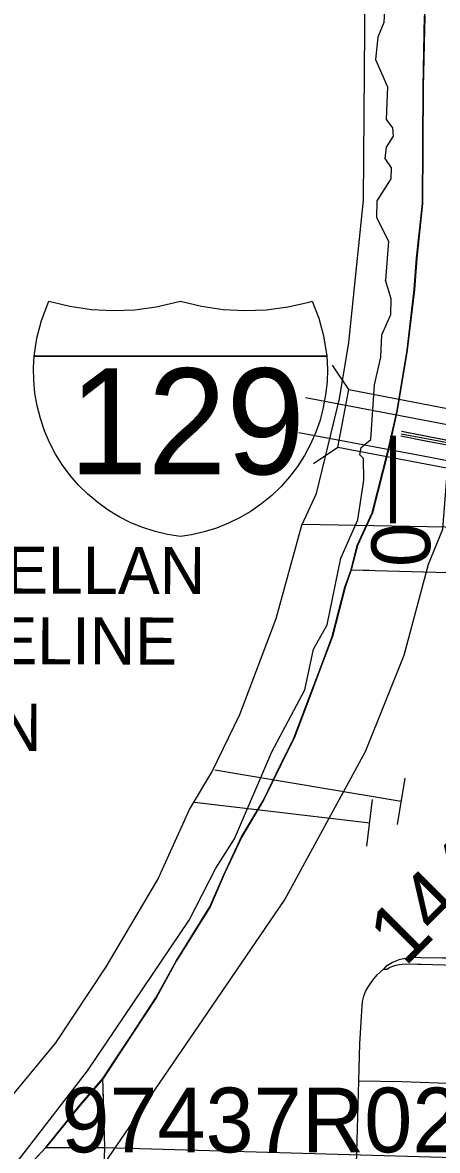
# Model space of a CAD drawing. Extents: x -157.2 to -99.3, y 12.2 to 46.2.
# Drawn here: x -147.831 to -147.125, y 32.094 to 34.011 of the extents above; entities that cross this region are included whole.
import ezdxf

# ---------------------------------------------------------------- set-up
doc = ezdxf.new("R2010")
doc.units = 0
for name, color, linetype in [('tdCoCityStreetMinor', 7, 'Continuous'), ('tdCoClipBndry', 7, 'Continuous'), ('tdCoCoBndry', 7, 'Continuous'), ('tdCoCorpBndry', 7, 'Continuous'), ('tdCoDivCarto', 7, 'Continuous'), ('tdCoHydroRiver', 7, 'Continuous'), ('tdCoInt', 7, 'Continuous'), ('tdCoIntCL', 7, 'Continuous'), ('tdCoIntRte', 7, 'Continuous'), ('tdCoPipe1', 7, 'Continuous'), ('tdCoPipe2', 7, 'Continuous'), ('tdCoPipeTxt', 7, 'Continuous'), ('tdCoSectLine', 7, 'Continuous'), ('tdCoSectLinePart', 7, 'Continuous'), ('tdCoShieldInt', 7, 'Continuous'), ('tdCoStBndry', 7, 'Continuous'), ('tdCoStBndryPart', 7, 'Continuous'), ('tdCoStrucNonDivPri', 7, 'Continuous'), ('tdCoStrucPriMaintName', 7, 'Continuous'), ('tdCoTwpBndryShd', 7, 'Continuous'), ('tdStHwyIntRefPost1', 7, 'Continuous'), ('tdStHwyPriRefPost1', 7, 'Continuous'), ('tdStHwyPriRefPost5', 7, 'Continuous')]:
    doc.layers.add(name, color=color, linetype=linetype)

msp = doc.modelspace()

# ---------------------------------------------------------------- linework, layer by layer
at = {"layer": 'tdCoCityStreetMinor'}
for points in [[(-147.1526, 32.4217), (-147.1619, 32.422), (-147.1677, 32.4219), (-147.1735, 32.4215), (-147.1792, 32.4207), (-147.1849, 32.4196), (-147.1904, 32.418), (-147.1959, 32.4161), (-147.2012, 32.4138), (-147.213, 32.407), (-147.2166, 32.4023)], [(-147.104, 32.4208), (-147.1162, 32.4209), (-147.1526, 32.4217)], [(-147.2536, 32.3307), (-147.2526, 32.3473), (-147.2504, 32.3564), (-147.2472, 32.3643), (-147.2425, 32.3729), (-147.2346, 32.3835), (-147.2274, 32.3927), (-147.2166, 32.4023)], [(-147.2166, 32.4023), (-147.2113, 32.4025), (-147.2063, 32.4051), (-147.2011, 32.4072), (-147.1958, 32.4089), (-147.1903, 32.4102), (-147.1848, 32.4111), (-147.1792, 32.4115), (-147.1581, 32.4108), (-147.1528, 32.4107)], [(-147.1528, 32.4107), (-147.1129, 32.4096), (-147.1025, 32.4094)], [(-147.2585, 32.2127), (-147.2568, 32.2755), (-147.2536, 32.3307)], [(-147.2585, 32.2127), (-147.1855, 32.2112), (-147.0296, 32.206), (-146.9507, 32.205), (-146.9433, 32.206), (-146.9357, 32.2085), (-146.9251, 32.2136), (-146.9103, 32.2228), (-146.8992, 32.2304)], [(-147.2666, 31.9442), (-147.2657, 31.9729), (-147.2607, 32.1308), (-147.2585, 32.2127)]]:
    msp.add_lwpolyline(points, dxfattribs=at)
at = {"layer": 'tdCoClipBndry'}
msp.add_lwpolyline([(-148.0503, 31.9701), (-147.9194, 32.1023), (-147.7742, 32.2769), (-147.6886, 32.4064), (-147.6009, 32.5545), (-147.5467, 32.6737), (-147.509, 32.7371), (-147.4609, 32.835), (-147.3992, 32.9986), (-147.3554, 33.1568), (-147.3309, 33.2109), (-147.2916, 33.3716), (-147.2757, 33.4676), (-147.2505, 33.7095), (-147.2477, 34.073)], dxfattribs=at)
at = {"layer": 'tdCoCoBndry'}
msp.add_lwpolyline([(-147.8297, 32.0582), (-147.7914, 32.0994), (-147.7325, 32.1717), (-147.6943, 32.2166), (-147.6759, 32.2443), (-147.6445, 32.2918), (-147.6038, 32.3534), (-147.5697, 32.4162), (-147.5121, 32.5083), (-147.4879, 32.5636), (-147.4581, 32.6274), (-147.4211, 32.6894), (-147.3914, 32.7507), (-147.3691, 32.7952), (-147.3471, 32.8533), (-147.3236, 32.9156), (-147.304, 32.9676), (-147.2825, 33.0515), (-147.2718, 33.0812), (-147.2615, 33.1226), (-147.236, 33.1778), (-147.2081, 33.2872), (-147.1936, 33.3516), (-147.1766, 33.4543), (-147.1645, 33.5575), (-147.1603, 33.611), (-147.1506, 33.7039), (-147.1495, 33.902), (-147.1469, 34.0229)], dxfattribs=at)
at = {"layer": 'tdCoCorpBndry'}
msp.add_lwpolyline([(-147.1466, 34.0229), (-147.1491, 33.902), (-147.1502, 33.7039), (-147.1599, 33.611), (-147.1641, 33.5575), (-147.1762, 33.4543), (-147.1932, 33.3516), (-147.2078, 33.2872), (-147.2357, 33.1778), (-147.2611, 33.1226), (-147.2715, 33.0812), (-147.2821, 33.0515), (-147.3036, 32.9676), (-147.3232, 32.9156), (-147.3468, 32.8533), (-147.3687, 32.7952), (-147.391, 32.7507), (-147.4207, 32.6894), (-147.4578, 32.6274), (-147.4875, 32.5636), (-147.5118, 32.5083), (-147.5693, 32.4162), (-147.6034, 32.3534), (-147.6441, 32.2918), (-147.6756, 32.2443), (-147.6939, 32.2166), (-147.7321, 32.1717), (-147.791, 32.0994), (-147.8293, 32.0582)], dxfattribs=at)
at = {"layer": 'tdCoDivCarto'}
for points in [[(-147.187, 33.309), (-147.1478, 33.301), (-147.1172, 33.2952), (-147.0879, 33.2896)], [(-147.187, 33.309), (-147.1478, 33.301), (-147.1172, 33.2952), (-147.0879, 33.2896)], [(-147.1858, 33.316), (-147.1858, 33.316)], [(-147.0815, 33.2958), (-147.1858, 33.316)], [(-147.0815, 33.2958), (-147.1858, 33.316)], [(-147.1858, 33.316), (-147.1858, 33.316)]]:
    msp.add_lwpolyline(points, dxfattribs=at)
at = {"layer": 'tdCoHydroRiver'}
for points in [[(-147.7589, 31.9734), (-147.5314, 32.3052), (-147.3851, 32.5197), (-147.2471, 32.7723), (-147.1815, 32.9359), (-147.1399, 33.0908), (-147.1158, 33.15), (-147.0822, 33.5785), (-147.0631, 33.7215), (-147.0603, 33.8036), (-147.0667, 33.8954), (-147.0881, 34.0556)], [(-147.2147, 34.0442), (-147.2159, 34.0111), (-147.2262, 33.9862), (-147.2306, 33.9484), (-147.2101, 33.9019), (-147.212, 33.8467), (-147.2014, 33.8321), (-147.2003, 33.8179), (-147.212, 33.7993), (-147.2143, 33.7804), (-147.2038, 33.7643), (-147.2044, 33.7454), (-147.2278, 33.7083), (-147.2287, 33.6799), (-147.208, 33.6397), (-147.2134, 33.5735)], [(-147.8919, 32.008), (-147.7202, 32.2295), (-147.5473, 32.4858), (-147.5017, 32.5742), (-147.47, 32.6237), (-147.4065, 32.7715), (-147.3508, 32.877), (-147.3359, 32.946), (-147.3123, 32.9878), (-147.2895, 33.1007), (-147.2605, 33.1661), (-147.2503, 33.2336), (-147.2506, 33.27), (-147.2567, 33.2765), (-147.2547, 33.2891), (-147.2384, 33.3027), (-147.2321, 33.3957), (-147.221, 33.4427), (-147.2198, 33.4805), (-147.2044, 33.5148), (-147.2035, 33.5416), (-147.2134, 33.5735)]]:
    msp.add_lwpolyline(points, dxfattribs=at)
at = {"layer": 'tdCoInt'}
for points in [[(-147.3493, 33.3737), (-147.1289, 33.3319), (-147.0816, 33.3229), (-147.0771, 33.322), (-147.0534, 33.3174), (-146.9907, 33.3055), (-146.9535, 33.2984), (-146.93, 33.2939), (-146.9002, 33.2881)], [(-147.3605, 33.3147), (-147.1401, 33.273), (-147.0935, 33.2641), (-147.089, 33.2632), (-147.0647, 33.2584), (-147.0019, 33.2466), (-146.9647, 33.2395), (-146.9415, 33.235), (-146.9118, 33.2292)]]:
    msp.add_lwpolyline(points, dxfattribs=at)
at = {"layer": 'tdCoIntCL'}
msp.add_lwpolyline([(-147.1869, 33.3124), (-147.1345, 33.3025), (-147.0876, 33.2935)], dxfattribs=at)
at = {"layer": 'tdCoIntRte'}
for points in [[(-147.1874, 33.309), (-147.1482, 33.301), (-147.1176, 33.2952), (-147.0883, 33.2896), (-147.0345, 33.2792), (-146.9967, 33.2721), (-146.9733, 33.2677), (-146.973, 33.2676), (-146.9704, 33.2671), (-146.9601, 33.2651), (-146.9132, 33.2561)], [(-147.1874, 33.309), (-147.1482, 33.301), (-147.1176, 33.2952), (-147.0883, 33.2896), (-147.0345, 33.2792), (-146.9967, 33.2721), (-146.9733, 33.2677), (-146.973, 33.2676), (-146.9704, 33.2671), (-146.9601, 33.2651), (-146.9132, 33.2561)], [(-146.913, 33.2638), (-146.9583, 33.2723), (-146.9961, 33.2794), (-147.0385, 33.2874), (-147.0401, 33.2877), (-147.0518, 33.2899), (-147.0824, 33.2959), (-147.1862, 33.316), (-147.1862, 33.316)], [(-146.913, 33.2638), (-146.9583, 33.2723), (-146.9961, 33.2794), (-147.0381, 33.2873), (-147.0401, 33.2877), (-147.0518, 33.2899), (-147.0819, 33.2958), (-147.1862, 33.316), (-147.1862, 33.316)]]:
    msp.add_lwpolyline(points, dxfattribs=at)
at = {"layer": 'tdCoPipe1'}
msp.add_line((-147.1931, 32.6481), (-147.1797, 32.7272), dxfattribs=at)
msp.add_lwpolyline([(-147.5037, 32.7413), (-147.1864, 32.6877)], dxfattribs=at)
at = {"layer": 'tdCoPipe2'}
msp.add_line((-147.2449, 32.6113), (-147.2355, 32.6909), dxfattribs=at)
msp.add_lwpolyline([(-147.5381, 32.6863), (-147.2402, 32.6511)], dxfattribs=at)
at = {"layer": 'tdCoSectLine'}
for points in [[(-147.1477, 34.0775), (-147.1469, 34.0229), (-147.1495, 33.902), (-147.1506, 33.7039), (-147.1603, 33.611), (-147.1645, 33.5575), (-147.1766, 33.4543), (-147.1936, 33.3516), (-147.2081, 33.2872), (-147.236, 33.1778), (-147.2615, 33.1226), (-147.2718, 33.0812)], [(-147.2718, 33.0812), (-147.2825, 33.0515), (-147.304, 32.9676), (-147.3236, 32.9156), (-147.3471, 32.8533), (-147.3691, 32.7952), (-147.3914, 32.7507), (-147.4211, 32.6894), (-147.4581, 32.6274), (-147.4879, 32.5636), (-147.5121, 32.5083), (-147.5697, 32.4162), (-147.6038, 32.3534), (-147.6445, 32.2918), (-147.6759, 32.2443), (-147.6943, 32.2166)], [(-147.2718, 33.0812), (-146.6146, 33.0629)], [(-147.6943, 32.2166), (-147.7325, 32.1717), (-147.7914, 32.0994)], [(-147.6908, 32.0994), (-147.6943, 32.2166)], [(-147.7914, 32.0994), (-147.8297, 32.0582), (-147.8369, 32.0435), (-147.9802, 31.8988), (-148.0361, 31.8453), (-148.112, 31.7803), (-148.1715, 31.728), (-148.2711, 31.6411), (-148.3233, 31.5956), (-148.3755, 31.5548), (-148.429, 31.5044), (-148.4763, 31.46), (-148.5085, 31.4266), (-148.5541, 31.3804), (-148.5886, 31.3288), (-148.6141, 31.2907), (-148.6531, 31.2324), (-148.6721, 31.2042), (-148.7009, 31.1454)], [(-147.7914, 32.0994), (-147.6977, 32.0994), (-147.6908, 32.0994)], [(-147.7238, 31.1053), (-147.6908, 32.0994)], [(-147.6908, 32.0994), (-146.6609, 32.0697)]]:
    msp.add_lwpolyline(points, dxfattribs=at)
at = {"layer": 'tdCoSectLinePart'}
for points in [[(-147.1477, 33.9848), (-147.1495, 33.902), (-147.1506, 33.7039), (-147.1603, 33.611), (-147.1645, 33.5575), (-147.1766, 33.4543), (-147.1936, 33.3516), (-147.2081, 33.2872), (-147.236, 33.1778), (-147.2615, 33.1226), (-147.2718, 33.0812)], [(-147.2718, 33.0812), (-147.2825, 33.0515), (-147.304, 32.9676), (-147.3236, 32.9156), (-147.3471, 32.8533), (-147.3691, 32.7952), (-147.3914, 32.7507), (-147.4211, 32.6894), (-147.4581, 32.6274), (-147.4879, 32.5636), (-147.5121, 32.5083), (-147.5697, 32.4162), (-147.6038, 32.3534), (-147.6445, 32.2918), (-147.6759, 32.2443), (-147.6943, 32.2166)], [(-147.2718, 33.0812), (-147.2412, 33.0804)], [(-147.6943, 32.2166), (-147.7325, 32.1717), (-147.7914, 32.0994)], [(-147.6922, 32.146), (-147.6943, 32.2166)], [(-147.7914, 32.0994), (-147.8297, 32.0582), (-147.8369, 32.0435), (-147.9802, 31.8988), (-148.0361, 31.8453), (-148.112, 31.7803), (-148.1715, 31.728), (-148.2711, 31.6411), (-148.3233, 31.5956), (-148.3755, 31.5548), (-148.429, 31.5044), (-148.4763, 31.46), (-148.5085, 31.4266), (-148.5541, 31.3804), (-148.5886, 31.3288), (-148.6141, 31.2907), (-148.6531, 31.2324), (-148.6721, 31.2042), (-148.7009, 31.1454)], [(-147.7914, 32.0994), (-147.7391, 32.0994)]]:
    msp.add_lwpolyline(points, dxfattribs=at)
at = {"layer": 'tdCoShieldInt'}
msp.add_line((-147.8104, 33.4443), (-147.3138, 33.4443), dxfattribs=at)
for points in [[(-147.5622, 33.1376), (-147.5839, 33.141), (-147.6053, 33.1461), (-147.6262, 33.1529), (-147.6466, 33.1612), (-147.6662, 33.1711), (-147.685, 33.1825), (-147.7029, 33.1954), (-147.7197, 33.2095), (-147.7353, 33.2249), (-147.7498, 33.2415), (-147.7629, 33.2592), (-147.7745, 33.2778), (-147.7847, 33.2973), (-147.7934, 33.3175), (-147.8005, 33.3383), (-147.8059, 33.3596), (-147.8097, 33.3813), (-147.8118, 33.4032), (-147.8121, 33.4252), (-147.8111, 33.4443), (-147.8066, 33.475), (-147.7988, 33.5051), (-147.7862, 33.5376), (-147.7503, 33.5289), (-147.7137, 33.5236), (-147.6768, 33.5216), (-147.6399, 33.5231), (-147.6033, 33.5279), (-147.5622, 33.5376), (-147.5263, 33.5289), (-147.4897, 33.5236), (-147.4529, 33.5216), (-147.4159, 33.5231), (-147.3793, 33.5279), (-147.3433, 33.5362), (-147.3382, 33.5376), (-147.3268, 33.5087), (-147.3186, 33.4787), (-147.3133, 33.4443), (-147.3122, 33.4223), (-147.3128, 33.4003), (-147.3151, 33.3785), (-147.3191, 33.3569), (-147.3247, 33.3356), (-147.332, 33.3149), (-147.3409, 33.2947), (-147.3513, 33.2754), (-147.3632, 33.2569), (-147.3764, 33.2393), (-147.391, 33.2229), (-147.4068, 33.2076), (-147.4238, 33.1936), (-147.4418, 33.181), (-147.4607, 33.1698), (-147.4804, 33.1601), (-147.5009, 33.1519), (-147.5218, 33.1454), (-147.5433, 33.1405)], [(-147.3133, 33.4443), (-147.8111, 33.4443), (-147.8066, 33.475), (-147.7988, 33.5051), (-147.7862, 33.5376), (-147.7503, 33.5289), (-147.7137, 33.5236), (-147.6768, 33.5216), (-147.6399, 33.5231), (-147.6033, 33.5279), (-147.5622, 33.5376), (-147.5263, 33.5289), (-147.4897, 33.5236), (-147.4529, 33.5216), (-147.4159, 33.5231), (-147.3793, 33.5279), (-147.3433, 33.5362), (-147.3382, 33.5376), (-147.3268, 33.5087), (-147.3186, 33.4787)], [(-147.5622, 33.1376), (-147.5839, 33.141), (-147.6053, 33.1461), (-147.6262, 33.1529), (-147.6466, 33.1612), (-147.6662, 33.1711), (-147.685, 33.1825), (-147.7029, 33.1954), (-147.7197, 33.2095), (-147.7353, 33.2249), (-147.7498, 33.2415), (-147.7629, 33.2592), (-147.7745, 33.2778), (-147.7847, 33.2973), (-147.7934, 33.3175), (-147.8005, 33.3383), (-147.8059, 33.3596), (-147.8097, 33.3813), (-147.8118, 33.4032), (-147.8121, 33.4252), (-147.8111, 33.4443), (-147.3133, 33.4443), (-147.3122, 33.4223), (-147.3128, 33.4003), (-147.3151, 33.3785), (-147.3191, 33.3569), (-147.3247, 33.3356), (-147.332, 33.3149), (-147.3409, 33.2947), (-147.3513, 33.2754), (-147.3632, 33.2569), (-147.3764, 33.2393), (-147.391, 33.2229), (-147.4068, 33.2076), (-147.4238, 33.1936), (-147.4418, 33.181), (-147.4607, 33.1698), (-147.4804, 33.1601), (-147.5009, 33.1519), (-147.5218, 33.1454), (-147.5433, 33.1405)]]:
    msp.add_lwpolyline(points, close=True, dxfattribs=at)
at = {"layer": 'tdCoStBndry'}
msp.add_lwpolyline([(-147.1469, 34.0229), (-147.1495, 33.902), (-147.1506, 33.7039), (-147.1603, 33.611), (-147.1645, 33.5575), (-147.1766, 33.4543), (-147.1936, 33.3516), (-147.2081, 33.2872), (-147.236, 33.1778), (-147.2615, 33.1226), (-147.2718, 33.0812), (-147.2825, 33.0515), (-147.304, 32.9676), (-147.3236, 32.9156), (-147.3471, 32.8533), (-147.3691, 32.7952), (-147.3914, 32.7507), (-147.4211, 32.6894), (-147.4581, 32.6274), (-147.4879, 32.5636), (-147.5121, 32.5083), (-147.5697, 32.4162), (-147.6038, 32.3534), (-147.6445, 32.2918), (-147.6759, 32.2443), (-147.6943, 32.2166), (-147.7325, 32.1717), (-147.7914, 32.0994), (-147.8297, 32.0582)], dxfattribs=at)
at = {"layer": 'tdCoStBndryPart'}
msp.add_lwpolyline([(-147.1477, 33.9848), (-147.1495, 33.902), (-147.1506, 33.7039), (-147.1603, 33.611), (-147.1645, 33.5575), (-147.1766, 33.4543), (-147.1936, 33.3516), (-147.2081, 33.2872), (-147.236, 33.1778), (-147.2615, 33.1226), (-147.2718, 33.0812), (-147.2825, 33.0515), (-147.304, 32.9676), (-147.3236, 32.9156), (-147.3471, 32.8533), (-147.3691, 32.7952), (-147.3914, 32.7507), (-147.4211, 32.6894), (-147.4581, 32.6274), (-147.4879, 32.5636), (-147.5121, 32.5083), (-147.5697, 32.4162), (-147.6038, 32.3534), (-147.6445, 32.2918), (-147.6759, 32.2443), (-147.6943, 32.2166), (-147.7325, 32.1717), (-147.7914, 32.0994), (-147.8297, 32.0582)], dxfattribs=at)
at = {"layer": 'tdCoStrucNonDivPri'}
for p, q in [((-147.2755, 33.3874), (-147.3036, 33.4288)), ((-147.2943, 33.2892), (-147.3357, 33.2611))]:
    msp.add_line(p, q, dxfattribs=at)
msp.add_lwpolyline([(-147.2755, 33.3874), (-147.0578, 33.3457), (-147.0766, 33.2475), (-147.2943, 33.2892)], close=True, dxfattribs=at)
at = {"layer": 'tdCoStrucPriMaintName'}
msp.add_line((-147.3545, 33.1589), (-147.0502, 33.1527), dxfattribs=at)
at = {"layer": 'tdCoTwpBndryShd'}
msp.add_lwpolyline([(-147.8297, 32.0582), (-147.7914, 32.0994), (-147.7325, 32.1717), (-147.6943, 32.2166), (-147.6759, 32.2443), (-147.6445, 32.2918), (-147.6038, 32.3534), (-147.5697, 32.4162), (-147.5121, 32.5083), (-147.4879, 32.5636), (-147.4581, 32.6274), (-147.4211, 32.6894), (-147.3914, 32.7507), (-147.3691, 32.7952), (-147.3471, 32.8533), (-147.3236, 32.9156), (-147.304, 32.9676), (-147.2825, 33.0515), (-147.2718, 33.0812), (-147.2615, 33.1226), (-147.236, 33.1778), (-147.2081, 33.2872), (-147.1936, 33.3516), (-147.1766, 33.4543), (-147.1645, 33.5575), (-147.1603, 33.611), (-147.1506, 33.7039), (-147.1495, 33.902), (-147.1469, 34.0229)], dxfattribs=at)

# ---------------------------------------------------------------- texts
at = {"layer": 'tdCoPipeTxt'}
for s, p in [('MAGELLAN ', (-148.1027, 33.041)), ('PIPELINE', (-148.0495, 32.9209)), ('NORTHERN', (-148.4047, 32.7745))]:
    msp.add_text(s, height=0.08, rotation=359.8875, dxfattribs=at).set_placement(p)
at = {"layer": 'tdCoShieldInt'}
msp.add_text('129', height=0.18, dxfattribs=at).set_placement((-147.7518, 33.2435))
at = {"layer": 'tdCoStrucPriMaintName'}
msp.add_text('97437R029', height=0.11, dxfattribs=at).set_placement((-147.7648, 32.091))
at = {"layer": 'tdStHwyIntRefPost1'}
msp.add_text('144‒‒', height=0.1, rotation=45, dxfattribs=at).set_placement((-147.1805, 32.4049))
at = {"layer": 'tdStHwyPriRefPost1'}
msp.add_text('‒‒0', height=0.1, rotation=270, dxfattribs=at).set_placement((-147.2374, 33.309))
at = {"layer": 'tdStHwyPriRefPost5'}
msp.add_text('‒‒0', height=0.1, rotation=270, dxfattribs=at).set_placement((-147.2374, 33.309))

doc.saveas('drawing.dxf')
